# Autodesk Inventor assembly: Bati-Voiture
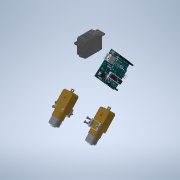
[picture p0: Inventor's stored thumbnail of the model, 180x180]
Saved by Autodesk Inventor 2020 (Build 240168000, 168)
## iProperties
Created: 2018-03
Part Number: Bati-Voiture
Material: Générique
Document SubType Name: Assembly
Designer: Bruno
Author: Bruno
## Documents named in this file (6)
- C:\Users\bruno\OneDrive\Bureau\Voiture-Inventor\Bati-Voiture.iam
- C:\Users\bruno\OneDrive\Bureau\Voiture-Inventor\Motoreducteur.iam
- C:\Users\bruno\OneDrive\Bureau\Voiture-Inventor\Motoreducteur-gauche.iam
- C:\Users\bruno\OneDrive\Bureau\Voiture-Inventor\Arduino\Carte Arduino UNO.iam
- C:\Users\bruno\OneDrive\Bureau\Voiture-Inventor\vis-M2.4.ipt
- C:\Users\bruno\OneDrive\Bureau\Voiture-Inventor\Servomoteur.ipt
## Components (9 placed, 5 different names)
1. Motoreducteur:1 [sub-assembly] — Affleurement:3, Placage:5, Placage:6
2. Motoreducteur-gauche:1 [sub-assembly] — Affleurement:3, Placage:7, Placage:8
3. Carte Arduino UNO:1 [sub-assembly] — Logement:5
4. vis-M2.4:5 — Logement:5
5. vis-M2.4:7 — Placage:5
6. vis-M2.4:9 — Placage:6
7. vis-M2.4:10 — Placage:8
8. vis-M2.4:11 — Placage:7
9. Servomoteur:1
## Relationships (6: Mate 4, Flush 1, Insert 1)
- Affleurement:3 [Flush]: Motoreducteur:1 ↔ Motoreducteur-gauche:1
- Logement:5 [Insert]: Carte Arduino UNO:1 ↔ vis-M2.4:5
- Placage:5 [Mate]: Motoreducteur:1 ↔ vis-M2.4:7
- Placage:6 [Mate]: Motoreducteur:1 ↔ vis-M2.4:9
- Placage:7 [Mate]: Motoreducteur-gauche:1 ↔ vis-M2.4:11
- Placage:8 [Mate]: Motoreducteur-gauche:1 ↔ vis-M2.4:10
